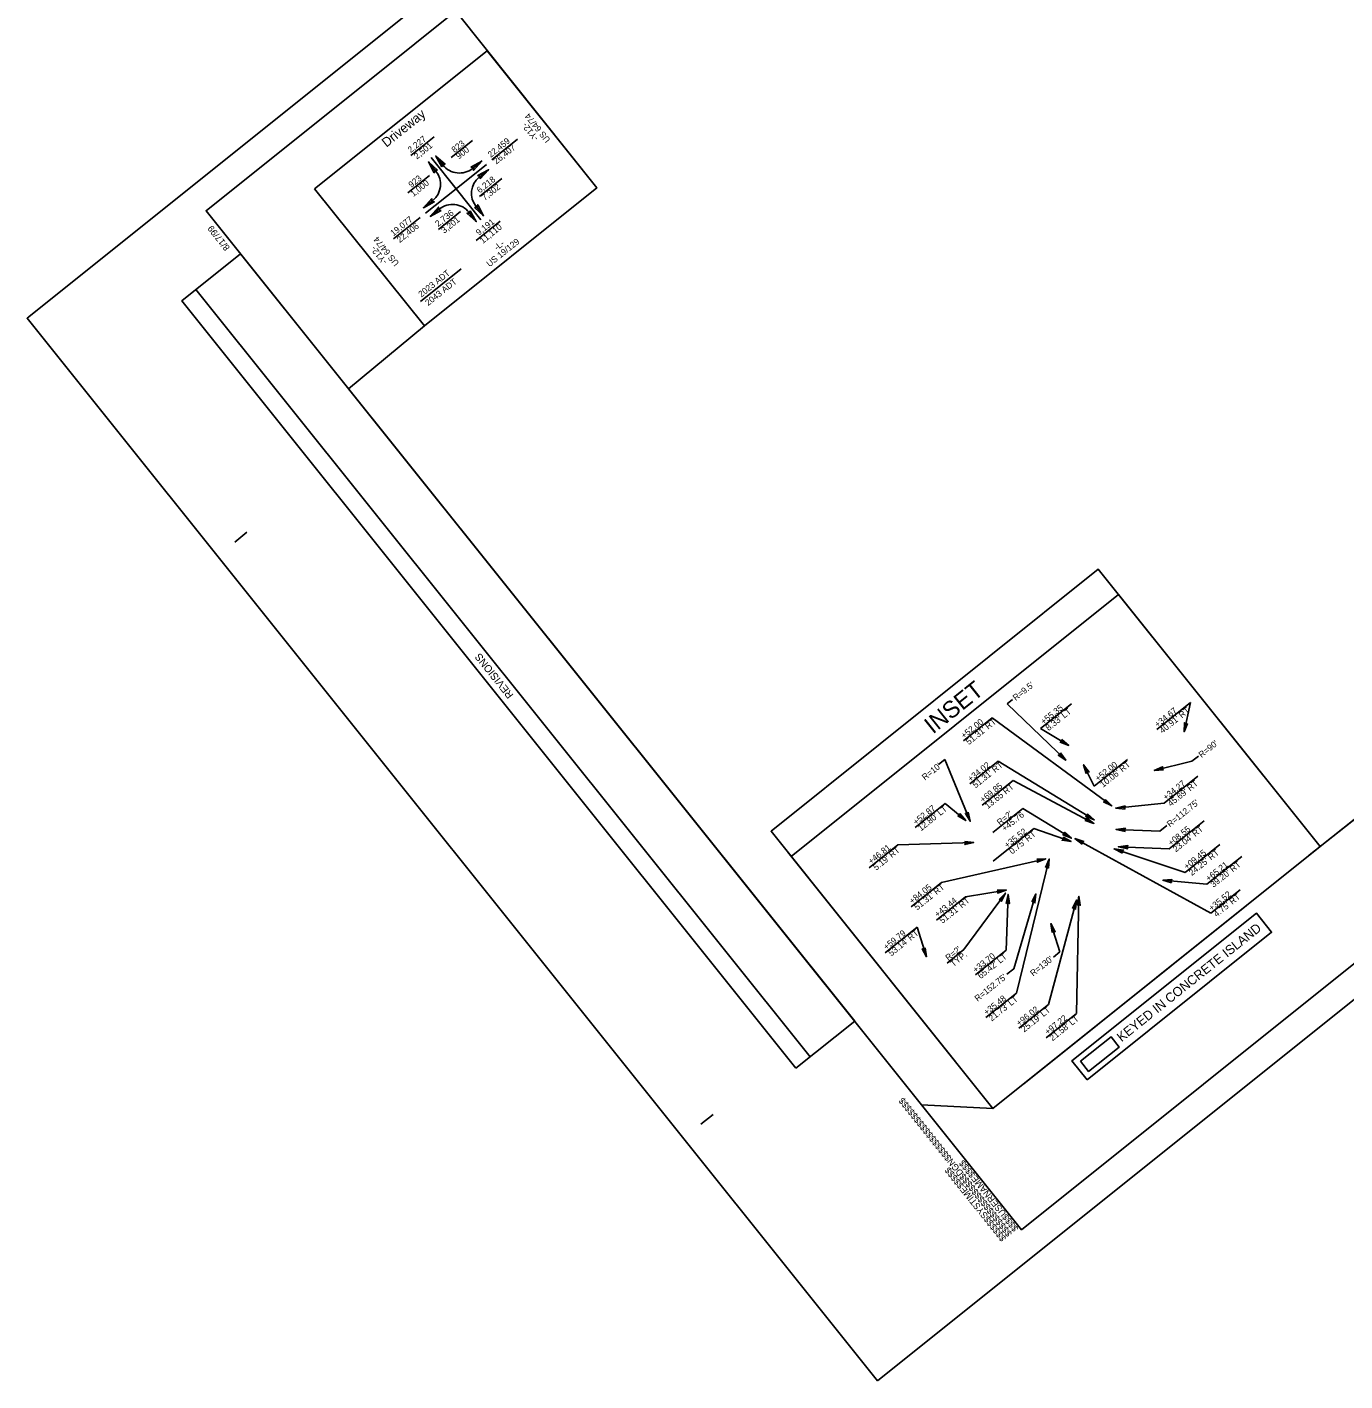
# Model space of a CAD drawing. Extents: x 472510 to 474509, y 505091 to 506998.
# Drawn here: x 472510 to 473570, y 505091 to 506180 of the extents above; entities that cross this region are included whole.
import ezdxf

# ---------------------------------------------------------------- set-up
doc = ezdxf.new("R2010")
doc.units = 0
for name, color, linetype in [('Default', 7, 'Continuous'), ('Matchline', 7, 'Continuous'), ('Prop Conc 5in Monolithic Keyed In Island', 7, 'Continuous'), ('Prop Dimension', 7, 'Continuous'), ('Prop Dimension Text', 7, 'Continuous'), ('Prop DSN Text', 7, 'Continuous'), ('Prop Grid Mask', 7, 'Continuous'), ('Prop Horizontal Alignment Curve and Spiral Data', 7, 'Continuous'), ('Prop PHM Traffic Signal CELL', 7, 'Continuous'), ('Prop Terminator CELL', 7, 'Continuous'), ('Sheet Block Revision CELL', 7, 'Continuous'), ('Sheet Clip Boundary CELL', 7, 'Continuous'), ('Sheet Plan CELL', 7, 'Continuous'), ('Sheet Plot Border Outside CELL', 7, 'Continuous')]:
    doc.layers.add(name, color=color, linetype=linetype)

msp = doc.modelspace()

# ---------------------------------------------------------------- linework, layer by layer
at = {"layer": 'Default'}
msp.add_lwpolyline([(473363.1, 505333.5), (473511.4, 505452.2), (473499.2, 505467.6), (473350.8, 505348.8)], close=True, dxfattribs=at)
at = {"layer": 'Matchline'}
msp.add_line((474315.3, 506128.4), (473541.8, 505514.2), dxfattribs=at)
at = {"layer": 'Prop Conc 5in Monolithic Keyed In Island'}
msp.add_lwpolyline([(473357.7, 505348.6), (473382.3, 505368.2), (473388.9, 505359.9), (473364.3, 505340.3)], close=True, dxfattribs=at)
at = {"layer": 'Prop Dimension'}
for p, q in [((473303.1, 505639.5), (473298.8, 505636.1)), ((473345.9, 505590.6), (473298.8, 505636.1)), ((473350.6, 505636.1), (473325.6, 505616.1)), ((473446.2, 505637), (473419.2, 505615.4)), ((473441.1, 505613.5), (473446.2, 505637)), ((473286.7, 505624.7), (473263.5, 505606.1)), ((473382.9, 505553.8), (473286.7, 505624.7)), ((473348.3, 505602.5), (473325.6, 505616.1)), ((473452.6, 505593.9), (473447.3, 505589.8)), ((473248.6, 505591.3), (473243.4, 505587.1)), ((473248.6, 505591.3), (473269, 505541.5)), ((473291.5, 505589.8), (473268.6, 505571.5)), ((473368.8, 505542.6), (473291.5, 505589.8)), ((473360.2, 505587), (473368.7, 505569.8)), ((473395.5, 505591.3), (473368.7, 505569.8)), ((473447.3, 505589.8), (473417.1, 505582.4)), ((473303.5, 505574.3), (473278.7, 505554.5)), ((473368.5, 505539.8), (473303.5, 505574.3)), ((473452.2, 505577.8), (473425, 505556)), ((473249, 505555.9), (473224.8, 505536.6)), ((473265.4, 505542.1), (473249, 505555.9)), ((473350.5, 505527.9), (473311.4, 505551.7)), ((473425, 505556), (473386.1, 505552.1)), ((473427.2, 505538), (473421.6, 505533.5)), ((473457.2, 505541.8), (473429.1, 505519.3)), ((473320.3, 505535.6), (473287.4, 505509.3)), ((473320.3, 505535.6), (473350.2, 505525.1)), ((473462.6, 505467.6), (473353.3, 505527.6)), ((473421.6, 505533.5), (473386.3, 505534.9)), ((473210.8, 505522.6), (473187.6, 505504.1)), ((473210.8, 505522.6), (473271.9, 505524.3)), ((473287.3, 505310.5), (473550.5, 505521.2)), ((473441.9, 505500.3), (473384.8, 505519.3)), ((473429.1, 505519.3), (473388.3, 505521)), ((473469.9, 505522.8), (473441.9, 505500.3)), ((473245.8, 505492.2), (473329.8, 505511.4)), ((473306.2, 505403.1), (473332.6, 505511.1)), ((473487.4, 505513.2), (473459.4, 505490.8)), ((473459.4, 505490.8), (473424, 505494)), ((473245.8, 505492.2), (473221.4, 505472.6)), ((473297.4, 505483.8), (473264, 505438.4)), ((473298, 505486.1), (473265.3, 505480.7)), ((473298, 505437.7), (473299.5, 505482.6)), ((473304.1, 505422.9), (473321.9, 505483.1)), ((473486.1, 505486.4), (473462.6, 505467.6)), ((473265.3, 505480.7), (473241.8, 505461.9)), ((473332, 505394.1), (473354.4, 505478.1)), ((473354.6, 505386.9), (473356.5, 505481.2)), ((473226.3, 505456.3), (473200.6, 505435.7)), ((473233.8, 505432.5), (473226.3, 505456.3)), ((473341.1, 505436.4), (473334, 505459.2)), ((473264, 505438.4), (473250.4, 505427.4)), ((473298, 505437.7), (473273.2, 505418)), ((473341.1, 505436.4), (473335.9, 505432.3)), ((473304.1, 505422.9), (473298.4, 505418.4)), ((473306.2, 505403.1), (473281.7, 505383.6)), ((473332, 505394.1), (473308.1, 505375)), ((473354.6, 505386.9), (473330.1, 505367.3))]:
    msp.add_line(p, q, dxfattribs=at)
at = {"layer": 'Prop Dimension Text'}
msp.add_line((473311.4, 505551.7), (473287.2, 505532.4), dxfattribs=at)
at = {"layer": 'Prop DSN Text'}
for p, q in [((472833.2, 506072.1), (472839.1, 506064.6)), ((472835.3, 506075.4), (472855.4, 506050.4)), ((472839.1, 506076.7), (472845, 506069.3)), ((472875.4, 506025.3), (472855.4, 506050.4)), ((472865.7, 506031.4), (472871.6, 506024)), ((472871.6, 506036.1), (472877.5, 506028.7))]:
    msp.add_line(p, q, dxfattribs=at)
for points in [[(472840.6, 506065.4), (472833.2, 506072), (472837.9, 506063.2), (472838.6, 506065.3)], [(472843.9, 506068.1), (472839.1, 506076.7), (472846.6, 506070.2), (472844.4, 506070)], [(472867.3, 506067.7), (472876, 506072.6), (472869.5, 506065.1), (472869.3, 506067.2)], [(472874.9, 506058.3), (472881.6, 506065.7), (472872.8, 506060.9), (472874.9, 506060.3)], [(472835.8, 506042.5), (472829.1, 506035.1), (472837.9, 506039.8), (472835.8, 506040.4)], [(472843.4, 506033), (472834.7, 506028.1), (472841.2, 506035.6), (472841.4, 506033.5)], [(472866.8, 506032.7), (472871.6, 506024), (472864.1, 506030.6), (472866.3, 506030.7)], [(472870.1, 506035.3), (472877.5, 506028.7), (472872.8, 506037.5), (472872.1, 506035.4)]]:
    msp.add_lwpolyline(points, close=True, dxfattribs=at)
for centre, start, end in [((472826.1, 506054.1), 308.7162, 38.7162), ((472858.1, 506079.8), 218.6261, 308.6261), ((472884.6, 506046.6), 128.7162, 218.7162), ((472852.6, 506021), 38.6261, 128.6261)]:
    msp.add_arc(centre, 16.8, start, end, dxfattribs=at)
at = {"layer": 'Prop Grid Mask'}
for p, q in [((473108.8, 505533.5), (473372, 505744.2)), ((473372, 505744.2), (473550.5, 505521.2)), ((473125, 505513.2), (473388.2, 505723.9)), ((473388.2, 505723.9), (473550.5, 505521.2)), ((473287.3, 505310.5), (473108.8, 505533.5)), ((473287.3, 505310.5), (473122.3, 505516.6)), ((473550.5, 505521.2), (473287.3, 505310.5)), ((473550.5, 505521.2), (473312.1, 505330.4))]:
    msp.add_line(p, q, dxfattribs=at)
msp.add_lwpolyline([(472741.6, 506050.3), (472880.4, 506161.4), (472968.6, 506051.1), (472829.9, 505940.1)], close=True, dxfattribs=at)
at = {"layer": 'Prop PHM Traffic Signal CELL'}
for p, q in [((472837.7, 506092.2), (472818.9, 506077.1)), ((472851.4, 506075.5), (472868.5, 506089.3)), ((472884.1, 506073.6), (472904.7, 506090.2)), ((472868.6, 506066.7), (472876.1, 506072.7)), ((472833.9, 506060.9), (472816.6, 506047)), ((472879.9, 506070), (472855.4, 506050.4)), ((472879.9, 506070), (472855.4, 506050.4)), ((472874.2, 506059.7), (472881.6, 506065.6)), ((472830.8, 506030.7), (472855.4, 506050.4)), ((472830.8, 506030.7), (472855.4, 506050.4)), ((472874.2, 506044.1), (472892.2, 506058.5)), ((472829.1, 506035.1), (472836.6, 506041)), ((472826.6, 506027.3), (472805.2, 506010.2)), ((472834.7, 506028.1), (472842.1, 506034.1)), ((472859, 506032), (472841.2, 506017.7)), ((472891, 506024.4), (472871.5, 506008.8)), ((472859.6, 505986), (472826.7, 505959.7))]:
    msp.add_line(p, q, dxfattribs=at)
msp.add_lwpolyline([(472741.6, 506050.3), (472880.4, 506161.4), (472968.6, 506051.1), (472829.9, 505940.1)], close=True, dxfattribs=at)
at = {"layer": 'Prop Terminator CELL'}
for points in [[(473443.8, 505620.2), (473441.1, 505613.5), (473441.4, 505620.8), (473442.4, 505619.6)], [(473342.8, 505607.3), (473348.3, 505602.5), (473341.5, 505605.1), (473342.9, 505605.7)], [(473341.6, 505596.5), (473345.9, 505590.6), (473339.8, 505594.7), (473341.3, 505595)], [(473362.3, 505580), (473360.2, 505587), (473364.6, 505581.1), (473363, 505581.3)], [(473424.4, 505582.9), (473417.1, 505582.4), (473423.8, 505585.4), (473423.2, 505583.9)], [(473377.8, 505559.1), (473382.9, 505553.8), (473376.3, 505557.1), (473377.8, 505557.5)], [(473267.4, 505548.7), (473269, 505541.5), (473265.1, 505547.8), (473266.6, 505547.4)], [(473393.7, 505551.3), (473386.1, 505552.1), (473393.6, 505553.9), (473392.7, 505552.5)], [(473260.7, 505547.7), (473265.4, 505542.1), (473259.1, 505545.8), (473260.6, 505546.2)], [(473362.7, 505544.3), (473368.5, 505539.8), (473361.5, 505542), (473362.9, 505542.7)], [(473363.3, 505547.4), (473368.8, 505542.6), (473362, 505545.3), (473363.4, 505545.9)], [(473343.8, 505528.7), (473350.2, 505525.1), (473342.9, 505526.3), (473344.2, 505527.2)], [(473344.9, 505532.7), (473350.4, 505527.9), (473343.6, 505530.6), (473345, 505531.2)], [(473359, 505523.1), (473353.3, 505527.6), (473360.3, 505525.2), (473358.8, 505524.6)], [(473393.7, 505533.3), (473386.3, 505534.9), (473393.9, 505535.9), (473392.8, 505534.6)], [(473264.7, 505525.3), (473271.9, 505524.3), (473264.7, 505522.8), (473265.6, 505524.1)], [(473391.5, 505515.8), (473384.8, 505519.3), (473392.4, 505518.3), (473391.1, 505517.3)], [(473395.8, 505519.4), (473388.3, 505521), (473395.9, 505522), (473394.9, 505520.7)], [(473322.5, 505511), (473329.8, 505511.4), (473323, 505508.6), (473323.6, 505510)], [(473329.7, 505504.4), (473332.6, 505511.1), (473332.1, 505503.8), (473331.1, 505505)], [(473329.7, 505504.4), (473332.6, 505511.1), (473332.1, 505503.8), (473331.1, 505505)], [(473431, 505492.1), (473424, 505494), (473431.3, 505494.6), (473430.3, 505493.4)], [(473290.7, 505486.2), (473298, 505486.1), (473291.1, 505483.7), (473291.8, 505485.1)], [(473292.2, 505478.7), (473297.4, 505483.8), (473294.2, 505477.2), (473293.7, 505478.7)], [(473298, 505475.4), (473299.5, 505482.6), (473300.5, 505475.3), (473299.3, 505476.2)], [(473318.7, 505476.6), (473321.9, 505483.1), (473321.1, 505475.8), (473320.1, 505477.1)], [(473351.4, 505471.4), (473354.4, 505478.1), (473353.8, 505470.7), (473352.8, 505472)], [(473355.1, 505474.1), (473356.5, 505481.2), (473357.6, 505474), (473356.4, 505474.9)], [(473335, 505451.9), (473334, 505459.2), (473337.4, 505452.6), (473335.9, 505453.1)], [(473232.8, 505439.8), (473233.8, 505432.5), (473230.4, 505439), (473231.9, 505438.5)]]:
    msp.add_lwpolyline(points, close=True, dxfattribs=at)
at = {"layer": 'Sheet Block Revision CELL'}
msp.add_line((473140.2, 505352), (472646.1, 505969.3), dxfattribs=at)
msp.add_lwpolyline([(473128.8, 505342.9), (472634.8, 505960.2), (472682.1, 505998), (473176.1, 505380.7)], close=True, dxfattribs=at)
at = {"layer": 'Sheet Clip Boundary CELL'}
msp.add_lwpolyline([(473777.7, 506709.4), (473669.3, 506844.9), (472855.1, 506193.3), (472968.6, 506051.1), (472829.9, 505940.1), (472769, 505889.4), (473229.9, 505313.5), (473287.3, 505310.5), (473108.8, 505533.5), (473372, 505744.2), (473550.5, 505521.2), (474139.2, 505988.5), (474128.7, 506014.5), (474324.3, 506183.3), (473855.2, 506771.5)], close=True, dxfattribs=at)
at = {"layer": 'Sheet Plan CELL'}
for p, q in [((472654.3, 506032.7), (472654.3, 506032.7)), ((472677.4, 505766.1), (472687.2, 505774)), ((473052.4, 505297.7), (473062.1, 505305.5)), ((473310.4, 505212.9), (473310.4, 505212.9))]:
    msp.add_line(p, q, dxfattribs=at)
msp.add_lwpolyline([(473825.5, 506970), (472654.3, 506032.7), (473310.4, 505212.9), (474481.5, 506150.2)], close=True, dxfattribs=at)
at = {"layer": 'Sheet Plot Border Outside CELL'}
msp.add_lwpolyline([(473194.5, 505091.3), (474508.9, 506143.2), (473824.7, 506998.1), (472510.3, 505946.2)], close=True, dxfattribs=at)

# ---------------------------------------------------------------- texts
at = {"layer": 'Prop Dimension'}
for s, p in [("R=90'", (473455.2, 505592.3)), ("R=2'", (473251.5, 505429)), ('TYP.', (473255.5, 505424.1)), ("R=130'", (473319.7, 505416.5))]:
    msp.add_text(s, height=5, rotation=38.7153, dxfattribs=at).set_placement(p)
at = {"layer": 'Prop Dimension Text'}
for s, p in [("R=9.5'", (473305.7, 505638.2)), ('+55.35', (473328.1, 505619)), ("51.31' RT", (473268, 505602.7)), ("8.33' LT", (473332.1, 505614)), ('+34.67', (473419.8, 505616.7)), ("40.91' RT", (473423.7, 505611.8)), ('+52.00', (473264, 505607.7)), ("R=10'", (473232.6, 505574.2)), ('+34.02', (473269.4, 505572.9)), ("51.31' RT", (473273.4, 505567.9)), ('+52.00', (473371.9, 505573.3)), ("10.06' RT", (473375.9, 505568.4)), ('+69.85', (473279.3, 505556.1)), ('13.65 RT', (473283.2, 505551.2)), ('+34.27', (473426.5, 505558.1)), ("45.69' RT", (473430.4, 505553.1)), ("R=112.75'", (473429.7, 505536.5)), ('+52.87', (473225.5, 505538.2)), ("12.80' LT", (473229.4, 505533.3)), ("R=2'", (473292.9, 505537.9)), ('+45.76', (473296.8, 505533)), ('+08.55', (473430.6, 505521.4)), ("23.04' RT", (473434.5, 505516.4)), ('+35.52', (473298.9, 505519.6)), ("0.75' RT", (473302.8, 505514.7)), ('+46.81', (473189.4, 505506.6)), ("5.19' RT", (473193.4, 505501.7)), ('+09.45', (473443.3, 505502.4)), ("24.25' RT", (473447.3, 505497.4)), ('+65.21', (473460.9, 505492.8)), ("39.20' RT", (473464.8, 505487.9)), ('+84.05', (473222.4, 505474.6)), ("51.31' RT", (473226.4, 505469.7)), ('+35.52', (473463.3, 505469)), ("4.75' RT", (473467.3, 505464.1)), ('+43.44', (473242.8, 505463.9)), ("51.31' RT", (473246.7, 505458.9)), ('+59.79', (473201.6, 505437.7)), ("53.14' RT", (473205.6, 505432.7)), ('+33.70', (473273.5, 505419.3)), ("65.42' LT", (473277.5, 505414.4)), ("R=152.75'", (473275, 505396.2)), ('+35.48', (473282.3, 505385.2)), ("21.73' LT", (473286.3, 505380.3)), ('+96.02', (473308.5, 505376.4)), ("25.19' LT", (473312.4, 505371.5)), ('+97.22', (473331.4, 505369.4)), ("21.58' LT", (473335.3, 505364.5))]:
    msp.add_text(s, height=5, rotation=38.6712, dxfattribs=at).set_placement(p)
at = {"layer": 'Prop DSN Text'}
msp.add_text('KEYED IN CONCRETE ISLAND', height=7.5, rotation=38.6712, dxfattribs=at).set_placement((473390.8, 505363.7))
at = {"layer": 'Prop Horizontal Alignment Curve and Spiral Data'}
msp.add_text('INSET', height=13.62, rotation=38.6712, dxfattribs=at).set_placement((473239, 505611.2))
at = {"layer": 'Prop PHM Traffic Signal CELL'}
for s, height, rotation, p in [('Driveway', 7.5, 38.6711, (472799.4, 506083.4)), ('US 64/74', 5, 128.6712, (472931.6, 506089.9)), ('2,227', 5, 38.6711, (472818.9, 506079)), ('-Y12-', 5, 128.6712, (472922.1, 506091.3)), ('2,501', 5, 38.6711, (472823.9, 506073.8)), ('823', 5, 38.7613, (472854.2, 506079)), ('900', 5, 38.7613, (472857.8, 506073.9)), ('22,459', 5, 38.6712, (472883.3, 506075.1)), ('26,407', 5, 38.6712, (472887.8, 506069.8)), ('923', 5, 38.581, (472819.5, 506050.9)), ('6,218', 5, 38.6712, (472874.5, 506046.5)), ('1,000', 5, 38.581, (472821.1, 506043.7)), ('7,302', 5, 38.6712, (472878.5, 506040.5)), ('19,077', 5, 38.6711, (472805, 506012)), ('2,736', 5, 38.6711, (472841, 506019.5)), ('3,201', 5, 38.6711, (472845.9, 506014.1)), ('22,406', 5, 38.6711, (472810.1, 506006.6)), ('9,191', 5, 38.6711, (472873.8, 506012.4)), ('11,110', 5, 38.6711, (472876.9, 506005.9)), ('US 64/74', 5, 128.6712, (472809.9, 505990.6)), ('US 19/129', 5, 38.6711, (472882.3, 505987.2)), ('-L-', 5, 38.6711, (472888.4, 506000.5)), ('-Y12-', 5, 128.6712, (472800.4, 505992)), ('2023 ADT', 5, 38.6711, (472827.5, 505962.8)), ('2043 ADT', 5, 38.6711, (472833, 505955.9))]:
    msp.add_text(s, height=height, rotation=rotation, dxfattribs=at).set_placement(p)
at = {"layer": 'Sheet Block Revision CELL'}
msp.add_text('REVISIONS', height=6, rotation=128.6712, dxfattribs=at).set_placement((472902, 505643.2))
at = {"layer": 'Sheet Plan CELL'}
for s, p in [('8/17/99', (472673.8, 506003.1)), ('$$$$$$$$$$$$$$$$DGN$$$$$$$$$$$$$$$$', (473303, 505209.9)), ('$$$$USERNAME$$$$', (473308.1, 505214)), ('$$$$$$SYSTIME$$$$$', (473298.3, 505206.1))]:
    msp.add_text(s, height=5.25, rotation=128.6712, dxfattribs=at).set_placement(p)

doc.saveas('drawing.dxf')
